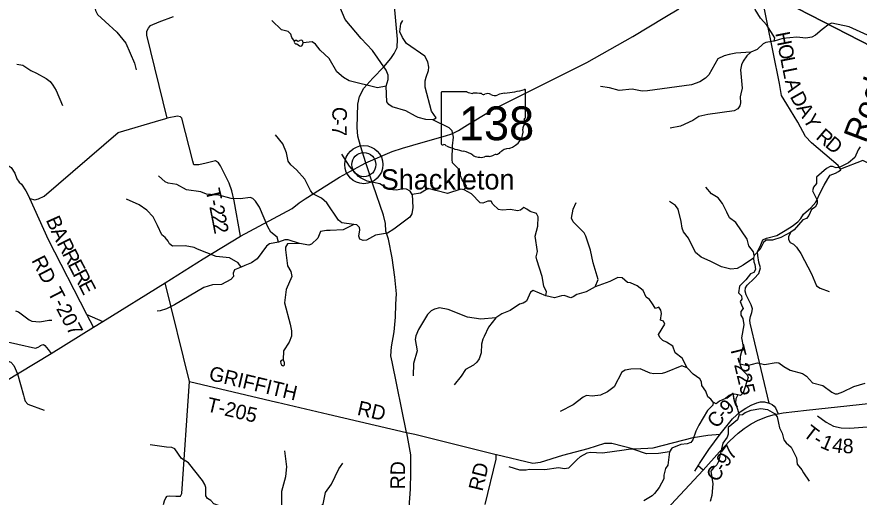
# Model space of a CAD drawing. Extents: x 1525783 to 1900577, y 218250 to 627376.
# Drawn here: x 1627391 to 1644767, y 423483 to 433381 of the extents above; entities that cross this region are included whole.
import ezdxf

# ---------------------------------------------------------------- set-up
doc = ezdxf.new("R2010")
doc.units = 0
for name, color, linetype in [('GM_X_County_Road', 7, 'Continuous'), ('GM_X_County_Road_Text', 7, 'Continuous'), ('GM_X_Minor_Lake', 7, 'Continuous'), ('GM_X_Minor_River', 7, 'Continuous'), ('GM_X_Minor_River_Text', 7, 'Continuous'), ('GM_X_State_Location', 7, 'Continuous'), ('GM_X_State_Route', 7, 'Continuous'), ('GM_X_State_Shield', 7, 'Continuous'), ('GM_X_Township', 7, 'Continuous'), ('GM_X_Township_Road', 7, 'Continuous'), ('GM_X_Township_Road_Text', 7, 'Continuous'), ('GM_X_Unincorporated', 7, 'Continuous'), ('GM_X_Unincorporated_Location', 7, 'Continuous'), ('GM_X_Unincorporated_Text', 7, 'Continuous'), ('GM_X_US_Route', 7, 'Continuous')]:
    doc.layers.add(name, color=color, linetype=linetype)

msp = doc.modelspace()

# ---------------------------------------------------------------- linework, layer by layer
at = {"layer": 'GM_X_County_Road'}
for points in [[(1634592, 430372), (1634482, 430723), (1634424, 430923), (1634408, 431098), (1634425, 431583), (1634461, 431737), (1634550, 431913), (1634736, 432118), (1634959, 432350), (1635109, 432520), (1635176, 432625), (1635236, 432753), (1635246, 432924), (1635122, 434281)], [(1626151, 430511), (1627001, 430355), (1627123, 430334), (1627134, 430332), (1627214, 430315), (1627272, 430279), (1627347, 430161), (1627394, 430043), (1627436, 429974), (1627487, 429934), (1627577, 429794), (1627662, 429639), (1627763, 429612), (1627836, 429628), (1627957, 429685), (1629482, 431001), (1630371, 431257), (1630495, 431295), (1630074, 433002), (1630074, 433084), (1630104, 433149), (1630148, 433206), (1630324, 433277), (1630622, 433389)], [(1635348, 421429), (1635515, 423648), (1635518, 423993), (1635516, 424358), (1635434, 424806), (1635431, 424818), (1635132, 426269), (1635105, 426398), (1635118, 426578), (1635176, 426887), (1635204, 427193), (1635208, 427462), (1635221, 427676), (1635186, 428018), (1635135, 428415), (1635059, 428798), (1635001, 428966), (1634997, 429122), (1634956, 429294), (1634741, 429912), (1634592, 430372)], [(1641476, 424175), (1641663, 424464), (1641898, 424778), (1642152, 425094), (1642309, 425238), (1642432, 425320), (1642542, 425379), (1642656, 425428), (1642733, 425445), (1642814, 425445), (1642883, 425427)], [(1642883, 425427), (1642907, 425421), (1642969, 425391), (1643015, 425357), (1643044, 425321), (1643094, 425203)], [(1641447, 424131), (1641460, 424150), (1641476, 424175)], [(1641378, 424018), (1641445, 424128)], [(1641549, 424042), (1641447, 424131)]]:
    msp.add_lwpolyline(points, dxfattribs=at)
at = {"layer": 'GM_X_Minor_Lake'}
for points in [[(1633114, 432861), (1633120, 432843), (1633138, 432827), (1633170, 432823), (1633195, 432806), (1633221, 432784), (1633243, 432780), (1633269, 432787), (1633285, 432805), (1633298, 432845), (1633290, 432881), (1633274, 432897), (1633253, 432902), (1633232, 432894), (1633220, 432884), (1633190, 432876), (1633163, 432895), (1633137, 432891), (1633118, 432879)], [(1633118, 432879), (1633114, 432861)], [(1632864, 426307), (1632846, 426297), (1632832, 426279), (1632838, 426239), (1632851, 426211), (1632869, 426199), (1632893, 426190), (1632911, 426208), (1632913, 426230), (1632910, 426260), (1632904, 426272)], [(1632904, 426272), (1632894, 426308), (1632882, 426313), (1632864, 426307)]]:
    msp.add_lwpolyline(points, dxfattribs=at)
at = {"layer": 'GM_X_Minor_River'}
for points in [[(1628698, 434128), (1628715, 434066), (1628908, 433875), (1628972, 433700), (1629014, 433510), (1629053, 433427), (1629211, 433287), (1629451, 433069), (1629642, 432837), (1629817, 432428), (1629855, 432293)], [(1643016, 432880), (1643027, 432952), (1642859, 433208), (1642731, 433352), (1642623, 433534), (1642550, 433777), (1642476, 433894), (1642095, 433985), (1641859, 433954), (1641672, 433864), (1641322, 433653), (1641270, 433644), (1641147, 433681), (1641021, 433665), (1640906, 433602)], [(1636619, 429816), (1636670, 429895), (1636578, 430023), (1636545, 430105), (1636540, 430173), (1636505, 430246), (1636380, 430376), (1636369, 430444), (1636381, 430720), (1636399, 430902), (1636371, 431031), (1636312, 431096), (1635970, 431256), (1635826, 431264), (1635673, 431310), (1635616, 431337), (1635417, 431442), (1635133, 431529), (1635063, 431574), (1635026, 431627), (1635008, 431954), (1635048, 432089), (1635051, 432177), (1635013, 432286), (1634728, 432686), (1634495, 432935), (1634161, 433326), (1633998, 433719)], [(1633118, 432879), (1633062, 432958), (1633044, 433028), (1632991, 433079), (1632848, 433111), (1632650, 433306)], [(1635970, 431256), (1636039, 431297), (1635947, 431437), (1635811, 431929), (1635813, 432063), (1635836, 432137), (1635883, 432274), (1635888, 432342), (1635870, 432453), (1635807, 432572), (1635427, 432829), (1635345, 432954), (1635292, 433075), (1635314, 433239), (1635351, 433307)], [(1645017, 432970), (1644558, 433174), (1644200, 433253), (1644147, 433233), (1644002, 433123), (1643863, 433003), (1643788, 432962), (1643670, 432939), (1643483, 432960), (1643195, 432932), (1643016, 432880), (1642962, 432873), (1642840, 432854), (1642786, 432823), (1642660, 432706), (1642532, 432654), (1642224, 432630), (1642084, 432604), (1641980, 432579), (1641851, 432519), (1641663, 432185), (1641600, 432120), (1641483, 432045), (1641307, 431981), (1640400, 431857), (1640292, 431850), (1640087, 431893), (1639815, 431867), (1639618, 431921), (1639433, 431946)], [(1635008, 431954), (1634828, 431922), (1634249, 432064), (1634130, 432129), (1633991, 432249), (1633831, 432526), (1633649, 432694), (1633555, 432819), (1633480, 432865), (1633298, 432845)], [(1642532, 432654), (1642451, 432581), (1642376, 432470), (1642337, 432396), (1642320, 432288), (1642353, 431915), (1642323, 431794), (1642310, 431732), (1642321, 431612), (1642308, 431548), (1642265, 431486), (1642191, 431445), (1641647, 431366), (1641462, 431330), (1641335, 431246), (1641078, 431129), (1640870, 431088)], [(1627390, 432404), (1627517, 432386), (1627681, 432274), (1627797, 432222), (1627999, 432111), (1628076, 432048), (1628137, 431977), (1628202, 431864), (1628331, 431556)], [(1634343, 429103), (1634093, 429138), (1634026, 429191), (1633789, 429549), (1633678, 429642), (1633549, 429704), (1633496, 429733), (1633447, 429803), (1633334, 430037), (1633162, 430230), (1633040, 430331), (1632985, 430404), (1632953, 430581), (1632878, 430764), (1632730, 430948)], [(1644788, 430702), (1644744, 430643), (1644674, 430484), (1644548, 430375), (1644357, 430279), (1644289, 430268), (1644220, 430297), (1644168, 430296), (1644093, 430259), (1643887, 430077), (1643890, 429945), (1643823, 429874), (1643802, 429798), (1643899, 429601), (1643898, 429535), (1643860, 429461), (1643785, 429414), (1643726, 429288), (1643677, 429225), (1643606, 429196), (1643426, 428990), (1643356, 428947), (1643150, 428835), (1642978, 428778), (1642848, 428779), (1642791, 428728), (1642724, 428595), (1642604, 428462), (1642584, 428406), (1642595, 428332), (1642612, 428278), (1642625, 428172), (1642596, 428110), (1642527, 428083), (1642432, 427960), (1642297, 427831), (1642281, 427697), (1642338, 427633), (1642347, 427564), (1642312, 427513), (1642338, 427444), (1642377, 427374), (1642328, 427308), (1642329, 427234), (1642370, 427164), (1642390, 427031), (1642339, 426769), (1642372, 426585), (1642333, 426459), (1642314, 426383), (1642306, 426227), (1642348, 426115), (1642455, 426005), (1642474, 425947), (1642374, 425636), (1642316, 425580), (1642264, 425591), (1642156, 425610), (1642084, 425579), (1642009, 425514), (1641883, 425462), (1641816, 425407), (1641752, 425437), (1641705, 425504), (1641644, 425551), (1641606, 425670), (1641523, 425787), (1641512, 425857), (1641477, 425922), (1641340, 426018), (1641216, 426147), (1641115, 426349), (1640974, 426459), (1640922, 426594), (1640791, 426674), (1640720, 426711), (1640657, 426772), (1640624, 426838), (1640756, 427047)], [(1635545, 429722), (1635502, 429787), (1635431, 429830), (1635359, 429835), (1635221, 429812), (1635067, 429826), (1634879, 429943), (1634620, 429994), (1634493, 430056), (1634441, 430089), (1634254, 430301), (1634093, 430552)], [(1632792, 428739), (1632759, 428843), (1632629, 428943), (1632568, 429052), (1632399, 429457), (1632317, 429586), (1632262, 429639), (1632206, 429661), (1632006, 429630), (1631815, 429639), (1631556, 429704), (1631304, 429729), (1631185, 429773), (1630894, 429815), (1630692, 429926), (1630512, 429954), (1630451, 429981), (1630385, 430040), (1630314, 430107)], [(1642604, 428462), (1642585, 428540), (1642491, 428660), (1642459, 428798), (1642221, 429140), (1642091, 429236), (1642034, 429353), (1641947, 429534), (1641856, 429651), (1641722, 429737), (1641604, 429871)], [(1638305, 427633), (1638316, 427711), (1638263, 427832), (1638226, 428033), (1638117, 428377), (1638107, 428435), (1638129, 428547), (1638085, 428862), (1638135, 429067), (1638148, 429259), (1638113, 429328), (1637980, 429370), (1637912, 429419), (1637849, 429454), (1637784, 429400), (1637720, 429387), (1637575, 429409), (1637403, 429397), (1637329, 429410), (1637212, 429518), (1637177, 429582), (1637107, 429581), (1637003, 429541), (1636951, 429549), (1636768, 429734), (1636619, 429816), (1636549, 429829), (1636276, 429744), (1636034, 429806), (1635904, 429837), (1635840, 429824), (1635715, 429746), (1635545, 429722), (1635560, 429449), (1635540, 429324), (1635497, 429256), (1635443, 429211), (1635170, 429006), (1635035, 428924), (1634787, 428883), (1634602, 428781), (1634532, 428772), (1634466, 428797), (1634449, 428863), (1634467, 428991), (1634458, 429041), (1634406, 429098), (1634343, 429103), (1634123, 428990), (1633852, 428977), (1633780, 428976), (1633652, 428960), (1633600, 428820), (1633472, 428696), (1633416, 428674), (1633221, 428707), (1632990, 428784), (1632922, 428789), (1632792, 428739), (1632606, 428703), (1632541, 428656), (1632352, 428394), (1632233, 428314), (1632092, 428255), (1632016, 428222), (1631884, 428168), (1631851, 428102), (1631858, 428028), (1631803, 427969), (1631610, 427867), (1631426, 427857), (1631246, 427804), (1630646, 427447), (1630475, 427363), (1630349, 427323), (1630283, 427314)], [(1632016, 428222), (1631957, 428313), (1631781, 428412), (1631500, 428441), (1631118, 428594), (1631049, 428631), (1630863, 428662), (1630599, 428657), (1630538, 428702), (1630513, 428761), (1630454, 428833), (1630383, 428888), (1630291, 429078), (1630200, 429257), (1630076, 429397), (1629917, 429507), (1629655, 429625)], [(1639322, 427814), (1639386, 427966), (1639278, 428311), (1639222, 428573), (1639130, 428860), (1639091, 428931), (1638870, 429158), (1638833, 429232), (1638867, 429420), (1638927, 429554)], [(1642584, 428406), (1642376, 428261), (1642251, 428192), (1642119, 428178), (1641926, 428229), (1641704, 428340), (1641509, 428430), (1641391, 428524), (1641243, 428822), (1641146, 428954), (1641115, 429026), (1641093, 429161), (1641032, 429420), (1640981, 429491), (1640857, 429576)], [(1643356, 428947), (1643312, 428853), (1643310, 428793), (1643343, 428729), (1643410, 428696), (1643473, 428635), (1643562, 428504), (1643784, 428082), (1643889, 427837), (1643964, 427788), (1644147, 427723)], [(1633221, 428707), (1632977, 428702), (1632936, 428633), (1632932, 428579), (1632975, 428252), (1633040, 428133), (1633064, 428030), (1632947, 427762), (1632912, 427488), (1633028, 427048), (1633054, 426913), (1633057, 426799), (1633011, 426677), (1632895, 426497), (1632882, 426313)], [(1640756, 427047), (1640733, 427111), (1640670, 427130), (1640689, 427266), (1640676, 427336), (1640633, 427395), (1640567, 427369), (1640492, 427489), (1640445, 427553), (1640374, 427606), (1640310, 427743), (1640189, 427841), (1640050, 427903), (1639988, 427910), (1639876, 428001), (1639790, 428010), (1639621, 427929), (1639322, 427814), (1639135, 427711), (1638946, 427661), (1638870, 427608), (1638818, 427593), (1638683, 427642), (1638628, 427633), (1638484, 427593), (1638305, 427633), (1638043, 427745), (1637990, 427708), (1637904, 427520), (1637836, 427483), (1637763, 427462), (1637568, 427327), (1637397, 427263), (1637270, 427180), (1637124, 426984), (1637034, 426793), (1637007, 426739), (1636976, 426633), (1636969, 426459), (1636926, 426332), (1636879, 426262), (1636812, 426205), (1636649, 426111), (1636556, 425978), (1636410, 425798)], [(1625281, 427403), (1625349, 427326), (1625544, 427258), (1625725, 427087), (1625859, 427063), (1625988, 427018), (1626172, 427023), (1626244, 427004), (1626371, 426824), (1626505, 426682), (1626780, 426481), (1626931, 426396), (1627074, 426343), (1627265, 426262), (1627326, 426199), (1627404, 426024), (1627528, 425582), (1627541, 425531), (1627564, 425461), (1627615, 425402), (1627955, 425278)], [(1627364, 427324), (1627426, 427305), (1627642, 427140), (1627701, 427113), (1627865, 427097), (1628049, 427131), (1628115, 427128)], [(1637270, 427180), (1636964, 427148), (1636687, 427190), (1636286, 427351), (1636110, 427382), (1636004, 427359), (1635936, 427322), (1635861, 427245), (1635677, 426941), (1635622, 426807), (1635611, 426731), (1635647, 426495), (1635574, 426237), (1635565, 425981)], [(1642306, 426227), (1642461, 426195), (1642668, 426248), (1642811, 426219), (1643057, 426255), (1643109, 426249), (1643216, 426175), (1643341, 426101), (1643600, 426030), (1643679, 425973), (1643807, 425841), (1644014, 425784), (1644200, 425644), (1644270, 425615), (1644322, 425614), (1644430, 425651), (1644657, 425762), (1644892, 425833)], [(1641216, 426147), (1641107, 426187), (1640772, 426053), (1640703, 426034), (1640533, 426022), (1640456, 426037), (1640247, 426124), (1640059, 426122), (1639943, 426098), (1639873, 426057), (1639711, 425757), (1639578, 425650), (1639431, 425584), (1639261, 425564), (1639141, 425580), (1639071, 425543), (1638869, 425387), (1638596, 425251)], [(1642264, 425591), (1642225, 425507), (1642216, 425435), (1642290, 425182), (1642255, 425074), (1642067, 424919), (1642064, 424782), (1642045, 424721), (1641957, 424592), (1641867, 424220), (1641830, 424147), (1641761, 424088), (1641710, 424018), (1641745, 423757), (1641730, 423517), (1641692, 423392)], [(1641752, 425437), (1641748, 425381), (1641636, 425267), (1641457, 424963), (1641395, 424843), (1641337, 424664), (1641294, 424610), (1641216, 424583), (1641090, 424567), (1640905, 424489), (1640852, 424420), (1640823, 424144), (1640772, 424072), (1640738, 423939), (1640739, 423861), (1640641, 423682), (1640548, 423557), (1640497, 423509), (1640324, 423405)], [(1642290, 425182), (1642362, 425185), (1642413, 425224), (1642539, 425273), (1642736, 425308), (1642879, 425290), (1643020, 425207), (1643075, 425136), (1643105, 425009), (1643124, 424913), (1643178, 424800), (1643211, 424665), (1643260, 424601), (1643363, 424515), (1643475, 424291), (1643490, 424163), (1643584, 424048), (1643619, 423987), (1643737, 423815)], [(1632345, 422144), (1632220, 422336), (1632056, 422655), (1632020, 422783), (1631993, 422980), (1631932, 423097), (1631865, 423142), (1631711, 423148), (1631652, 423189), (1631633, 423261), (1631571, 423302), (1631454, 423343), (1631395, 423414), (1631326, 423457), (1631290, 423512), (1631289, 423682), (1631267, 423742), (1631222, 423823), (1630930, 424189), (1630785, 424281), (1630648, 424477), (1630586, 424506), (1630480, 424512), (1630143, 424560)], [(1632855, 423225), (1632858, 423609), (1632943, 423911), (1632964, 424109), (1632920, 424436)], [(1640852, 424420), (1640630, 424379), (1640378, 424376), (1640122, 424464), (1640052, 424472), (1639922, 424454), (1639470, 424392), (1639222, 424405), (1639152, 424390), (1639011, 424314), (1638947, 424257), (1638768, 424077), (1638690, 424068), (1638563, 424085), (1638285, 424043), (1637957, 424051), (1637895, 424042), (1637769, 424040), (1637550, 424109)], [(1632311, 421666), (1632407, 421663), (1632465, 421692), (1632585, 421791), (1632847, 422162), (1632978, 422398), (1633046, 422572), (1633105, 422819), (1633177, 422952), (1633288, 423085), (1633540, 423240), (1633590, 423255), (1633662, 423284), (1633709, 423336), (1633756, 423580), (1633882, 423750), (1634030, 424065), (1634069, 424116), (1634113, 424180)]]:
    msp.add_lwpolyline(points, dxfattribs=at)
at = {"layer": 'GM_X_State_Route'}
for points in [[(1634592, 430372), (1635132, 430608), (1635348, 430676), (1635772, 430797), (1636232, 430931), (1636367, 430970), (1636503, 431041), (1636690, 431155), (1637153, 431436), (1637376, 431555), (1638752, 432242), (1639148, 432444), (1640097, 432976), (1640755, 433378), (1641048, 433544)], [(1626807, 425668), (1628096, 426444), (1628973, 426984), (1629162, 427101), (1630451, 427898), (1631237, 428395), (1632005, 428864), (1633068, 429429), (1633215, 429550), (1633339, 429634), (1634044, 430075), (1634500, 430322), (1634592, 430372)]]:
    msp.add_lwpolyline(points, dxfattribs=at)
at = {"layer": 'GM_X_State_Shield'}
for p, q in [((1636147, 431821), (1636147, 430764)), ((1636674, 431839), (1636164, 431839)), ((1637887, 431312), (1637887, 431865)), ((1637887, 431312), (1637887, 431312))]:
    msp.add_line(p, q, dxfattribs=at)
for centre, major_axis, start_param, end_param in [((1636167, 431823), (20.2, 0), 1.712693, 3.28349), ((1636795, 431962), (196, 0), 4.042523, 4.731795), ((1636860, 431246), (702, 0), 1.404758, 1.657858), ((1637020, 431828), (56.4, 0), 3.836095, 5.185415), ((1637102, 431706), (117, 0), 0.950623, 2.079405), ((1637254, 431874), (141, 0), 4.081561, 5.145723), ((1637503, 431516), (371, 0), 1.699011, 2.107814), ((1637268, 433279), (1845, 0), 4.814394, 5.042369), ((1637868, 431867), (19.4, 0), 6.141152, 7.989035), ((1637883, 431272), (30, 0), 1.883978, 3.671073), ((1637692, 431202), (180, 0), 5.934695, 6.695948), ((1637867, 431310), (20.7, 0), 5.05454, 6.418171), ((1637957, 431081), (131, 0), 2.387724, 3.262537), ((1637371, 431011), (462, 0), 5.101752, 6.440018), ((1636167, 430762), (20.3, 0), 3.00124, 4.508301), ((1636170, 430870), (155, 0), 4.665946, 4.897461), ((1636202, 430703), (56, 0), 0.519207, 1.627899), ((1636909, 431652), (1333, 0), 4.195997, 4.488961), ((1636511, 430289), (417, 0), 0.823519, 1.323587), ((1637245, 430662), (149, 0), 4.937069, 5.64225), ((1637566, 430467), (253, 0), 1.647645, 2.488434), ((1636962, 430698), (265, 0), 4.026481, 4.996735), ((1637115, 430333), (217, 0), 1.495662, 1.94098), ((1637135, 430619), (141, 0), 4.691044, 5.507374), ((1637262, 430516), (39.7, 0), 1.147584, 2.315152)]:
    msp.add_ellipse(centre, major_axis=major_axis, ratio=0.8, start_param=start_param, end_param=end_param, dxfattribs=at)
at = {"layer": 'GM_X_Township'}
for points in [[(1646572, 431971), (1642730, 433950)], [(1642730, 433950), (1646572, 431971)]]:
    msp.add_lwpolyline(points, dxfattribs=at)
at = {"layer": 'GM_X_Township_Road'}
for points in [[(1644381, 430241), (1644337, 430316), (1643784, 430783), (1643659, 430919), (1643499, 431208), (1643274, 431582), (1643168, 431759), (1643121, 432009), (1642730, 433950), (1642718, 434009)], [(1632005, 428864), (1631872, 429588), (1631824, 429798), (1631774, 429954), (1631595, 430312), (1631548, 430371), (1631489, 430417), (1631297, 430366), (1631142, 430332), (1631044, 430333), (1631022, 430404), (1630795, 431291), (1630767, 431324), (1630708, 431337), (1630495, 431295)], [(1646790, 429751), (1645543, 429470), (1645468, 429508), (1645331, 429759), (1645140, 430205), (1645100, 430275), (1645039, 430324), (1644973, 430354), (1644914, 430386), (1644845, 430418), (1644383, 430239)], [(1642907, 425421), (1642516, 427067), (1642512, 427129), (1642528, 427207), (1642550, 427290), (1642564, 427362), (1642539, 427449), (1642483, 427555), (1642436, 427650), (1642414, 427727), (1642420, 427797), (1642459, 427852), (1642599, 427987), (1642694, 428092), (1642731, 428206), (1642700, 428327), (1642678, 428460), (1642672, 428538), (1642738, 428685), (1642781, 428784), (1642852, 428820), (1643068, 428872), (1643243, 428979), (1643388, 429066), (1643504, 429154), (1643566, 429229), (1643621, 429312), (1643767, 429448), (1643870, 429561), (1643974, 429781), (1644042, 429915), (1644121, 430041), (1644169, 430118), (1644277, 430159), (1644340, 430194), (1644389, 430228), (1644383, 430239), (1644381, 430241)], [(1628973, 426984), (1628837, 427247), (1628042, 428786), (1627662, 429639)], [(1616931, 429427), (1618599, 428816), (1620137, 428247), (1620682, 428129), (1622683, 427696), (1622788, 427673), (1626264, 426897), (1627041, 426719), (1627774, 426551), (1627829, 426576), (1627880, 426604), (1627880, 426605)], [(1630414, 423329), (1630414, 423330), (1630435, 423407), (1630462, 423470), (1630493, 423500), (1630548, 423510), (1630668, 423501), (1630744, 423501), (1630770, 423506), (1630795, 423557), (1630953, 425863), (1630451, 427898)], [(1628837, 427247), (1629162, 427101)], [(1627880, 426605), (1627916, 426623), (1627938, 426629), (1627968, 426610), (1628036, 426526), (1628096, 426444)], [(1630953, 425863), (1632755, 425440), (1632764, 425438)], [(1632764, 425438), (1633816, 425191), (1635431, 424818), (1635601, 424779), (1637278, 424365), (1637288, 424362), (1638035, 424181), (1638190, 424207), (1638653, 424348), (1639174, 424488), (1639518, 424592), (1639664, 424596), (1640120, 424481), (1640407, 424489), (1640517, 424496), (1641341, 424710), (1641643, 424760), (1641898, 424778)], [(1643907, 425159), (1644083, 425026), (1644236, 424944), (1644395, 424909), (1644571, 424905), (1645024, 424938), (1645154, 424973), (1645250, 425028), (1645343, 425110), (1645383, 425152)], [(1637052, 423329), (1637278, 424268), (1637278, 424365), (1637278, 424369)]]:
    msp.add_lwpolyline(points, dxfattribs=at)
at = {"layer": 'GM_X_Unincorporated'}
for radius in [393, 249]:
    msp.add_circle((1634549, 430336), radius, dxfattribs=at)
at = {"layer": 'GM_X_Unincorporated_Location'}
msp.add_line((1634549, 430336), (1634549, 430336), dxfattribs=at)
at = {"layer": 'GM_X_US_Route'}
msp.add_lwpolyline([(1640793, 423231), (1641549, 424042), (1641888, 424416), (1642101, 424640), (1642269, 424800), (1642396, 424895), (1642540, 424992), (1642685, 425067), (1642874, 425142), (1642996, 425178), (1643094, 425203), (1643201, 425221), (1643683, 425274), (1644766, 425393), (1645503, 425474), (1645766, 425521), (1645969, 425576), (1646183, 425637), (1646335, 425694)], dxfattribs=at)

# ---------------------------------------------------------------- texts
at = {"layer": 'GM_X_County_Road_Text'}
for s, rotation, p in [('C', 267.6303, (1633906, 431531)), ('-', 268.4724, (1633896, 431280)), ('7', 271.5726, (1633893, 431139)), ('7', 37.7416, (1642186, 425279)), ('9', 43.9962, (1642061, 425158)), ('C', 50.9759, (1641833, 424883)), ('-', 48.9063, (1641985, 425071)), ('7', 53.102, (1642143, 424232)), ('9', 54.7019, (1642038, 424083)), ('RD', 89.5515, (1635396, 423643)), ('C', 58.1911, (1641843, 423775)), ('-', 56.4214, (1641971, 423982))]:
    msp.add_text(s, height=300, rotation=rotation, dxfattribs=at).set_placement(p)
at = {"layer": 'GM_X_Minor_River_Text'}
msp.add_text('Rocky', height=499.9, rotation=69.302, dxfattribs=at).set_placement((1644899, 430759))
at = {"layer": 'GM_X_State_Location'}
msp.add_text('138', height=1, rotation=0, dxfattribs=at).set_placement((1636645, 431149))
for s in ['s', 'r']:
    msp.add_text(s, height=1, dxfattribs=at).set_placement((1636998, 431222))
at = {"layer": 'GM_X_State_Shield'}
msp.add_text('138', height=696.1, dxfattribs=at).set_placement((1636510, 430839))
at = {"layer": 'GM_X_Township_Road_Text'}
for s, rotation, p in [('H', 281.2353, (1643035, 433045)), ('O', 281.2335, (1643086, 432786)), ('L', 281.2339, (1643138, 432527)), ('L', 281.2714, (1643182, 432307)), ('A', 285.5537, (1643231, 432063)), ('D', 299.0392, (1643331, 431738)), ('A', 300.7055, (1643464, 431499)), ('Y', 299.1448, (1643598, 431274)), ('R', 319.2354, (1643856, 430882)), ('D', 319.9757, (1644046, 430719)), ('T', 283.449, (1631281, 429806)), ('-', 282.3586, (1631333, 429589)), ('2', 281.6855, (1631359, 429470)), ('B', 294.1801, (1627984, 429197)), ('2', 281.0359, (1631396, 429290)), ('2', 280.845, (1631432, 429109)), ('A', 295.6397, (1628089, 428964)), ('R', 297.2228, (1628207, 428718)), ('R', 297.4132, (1628320, 428498)), ('RD', 297.2283, (1627685, 428364)), ('E', 297.4136, (1628434, 428279)), ('R', 297.4132, (1628537, 428080)), ('E', 297.4141, (1628651, 427861)), ('T-207', 297.4445, (1628021, 427705)), ('T-225', 283.6272, (1642096, 426581)), ('GRIFFITH', 346.6633, (1631335, 425899)), ('T-205', 346.7121, (1631289, 425256)), ('RD', 347.0418, (1634396, 425182)), ('T', 322.3201, (1643590, 424756)), ('-', 328.2054, (1643796, 424599)), ('1', 336.9424, (1643945, 424511)), ('4', 351.604, (1644195, 424416)), ('8', 0.5411, (1644429, 424386)), ('RD', 76.5619, (1636996, 423590))]:
    msp.add_text(s, height=300, rotation=rotation, dxfattribs=at).set_placement(p)
at = {"layer": 'GM_X_Unincorporated_Text'}
msp.add_text('Shackleton', height=417, rotation=0, dxfattribs=at).set_placement((1634898, 429823))

doc.saveas('drawing.dxf')
